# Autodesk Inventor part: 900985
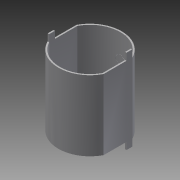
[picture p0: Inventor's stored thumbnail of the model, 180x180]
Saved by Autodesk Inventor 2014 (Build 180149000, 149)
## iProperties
Created: 2007-10
Part Number: 900985
Document SubType Name: Sheet Metal
Designer: TH
Density: 8.08 g/cm^3
Mass: 55.7852 g
Surface Area: 142.634 cm^2
Volume: 6.9041 cm^3
Material: Stainless Steel
Description: MOTOR SLEEVE
Sheet Metal Rule: Default
Appearance: Steel
Component Category: Electrical
Author: TH
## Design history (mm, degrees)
sketch "Sketch1"
  geometry: L1 (-20, 10.061)-(-20, -10.061); L2 (20, 10.061)-(20, -10.061); L3 (-19, 10.061)-(-19, -10.061); L4 (19, -10.062)-(19, 10.061); A1 r 22.5 centre (0, 0) between (-19.883, -10.531) and (19.883, -10.531); A2 r 22.5 centre (0, 0) between (19.883, 10.531) and (-19.883, 10.531); A3 r 21.5 centre (0, 0) between (-18.999, -10.063) and (19, -10.062); A4 r 21.5 centre (0, 0) between (18.999, 10.063) and (-18.999, 10.063); A5 r 0.005 centre (-18.995, 10.061) between (-18.999, 10.063) and (-19, 10.061); A6 r 0.005 centre (18.995, 10.061) between (19, 10.061) and (18.999, 10.063); A7 r 0.005 centre (-18.995, -10.061) between (-19, -10.061) and (-18.999, -10.063); A8 r 1.005 centre (-18.995, 10.061) between (-19.883, 10.531) and (-20, 10.061); A9 r 1.005 centre (-18.995, -10.061) between (-20, -10.061) and (-19.883, -10.531); A10 r 1.005 centre (18.995, -10.061) between (19.883, -10.531) and (20, -10.061); A11 r 1.005 centre (18.995, 10.061) between (20, 10.061) and (19.883, 10.531); 1 further point
  constraints: 22 point on circle, 14 tangent, 11 centre point, 8 end point, 5 equal radius, 2 parallel, 1 coincident, 1 vertical, 3 other
  dimensions: "d1" = 40 distance between parallel lines of L2 L1; "d2" = 20 distance from line of L2 point (0, 0) (= 0.5 x d1); "d3" = 22.5 radius of A2; "d4" = 1 distance between parallel lines of L1 L3; "d17" = 0.005 radius of A5; "d19" = 1.005 radius of A8; "d22" = 22.5 radius of A1 (= d3)
extrude "Extrusion1" new body sketch "Sketch1" stored distance "d5" = 50; taper "d6" = 0 deg
workplane "Work Plane1"
sketch "Sketch2"
  geometry: L1 (0, -35)-(0, 35) reference; L2 (-28, 0)-(28, 0) reference; L3 (19.883, 25)-(-19.883, 25) reference; L4 (-19.883, 25)-(19.883, 25) reference; L5 (-4, 25)-(-4, 10.887); L6 (-2.5, 10.021)-(-1.5, 10.598); L7 (1.5, 5.402)-(-3.5, 2.515); L8 (-4, 1.649)-(-4, 0); L9 (-4.1, 0)-(-4.1, 1.649); L10 (-3.55, 2.602)-(1.45, 5.489); L11 (-1.45, 10.511)-(-2.45, 9.934); L12 (-4.1, 10.887)-(-4.1, 25); L13 (-4, -25)-(-4, -10.887); L14 (-4.1, -10.887)-(-4.1, -25); L15 (-2.5, -10.021)-(-1.5, -10.598); L16 (-1.45, -10.511)-(-2.45, -9.934); L17 (-3.55, -2.602)-(1.45, -5.489); L18 (1.5, -5.402)-(-3.5, -2.515); L19 (-4, -1.649)-(-4, 0); L20 (-4.1, 0)-(-4.1, -1.649); L21 (-4, -25)-(-4.1, -25); L22 (-4.1, 25)-(-4, 25); L23 (20, 25)-(19.883, 25) reference; L24 (19.883, 25)-(20, 25) reference; L25 (-20, 25)-(-19.883, 25) reference; L26 (-19.883, 25)-(-20, 25) reference; A1 r 3 centre (0, 8) between (1.5, 5.402) and (-1.5, 10.598); A2 r 1 centre (-3, 10.887) between (-4, 10.887) and (-2.5, 10.021); A3 r 1 centre (-3, 1.649) between (-3.5, 2.515) and (-4, 1.649); A4 r 1.1 centre (-3, 1.649) between (-3.55, 2.602) and (-4.1, 1.649); A5 r 2.9 centre (0, 8) between (1.45, 5.489) and (-1.45, 10.511); A6 r 1.1 centre (-3, 10.887) between (-4.1, 10.887) and (-2.45, 9.934); A7 r 1 centre (-3, -10.887) between (-2.5, -10.021) and (-4, -10.887); A8 r 1.1 centre (-3, -10.887) between (-2.45, -9.934) and (-4.1, -10.887); A9 r 3 centre (0, -8) between (-1.5, -10.598) and (1.5, -5.402); A10 r 2.9 centre (0, -8) between (-1.45, -10.511) and (1.45, -5.489); A11 r 1.1 centre (-3, -1.649) between (-4.1, -1.649) and (-3.55, -2.602); A12 r 1 centre (-3, -1.649) between (-4, -1.649) and (-3.5, -2.515); 1 further point
  constraints: 36 end point, 24 point on circle, 17 symmetric about line, 12 centre point, 6 tangent, 3 parallel, 3 point on line, 2 collinear, 2 perpendicular, 12 other
  dimensions: "d8" = 60 deg angle of L6 L5; "d9" = 6 diameter of A1; "d11" = 4 distance between parallel lines of L1 L5; "d12" = 1 radius of A2; "d13" = 1 radius of A3; "d14" = 0.1 distance between parallel lines of L5 L12; "d21" = 14.11325 distance from line of A2.centre L3
cut "Cut1" sketch "Sketch2" dims "d15" = 3, "d16" = 0
sketch "Sketch3"
  geometry: L1 (-20, -10.061)-(-20, 10.061) reference; L2 (20, 10.061)-(20, -10.061) reference; L3 (18.995, -10.061)-(20, -10.061); L4 (20, -10.061)-(20, -6); L5 (20, -6)-(18.995, -6); L6 (18.995, -6)-(18.995, -10.061); L7 (-18.995, 10.061)-(-20, 10.061); L8 (-20, 10.061)-(-20, 6); L9 (-20, 6)-(-18.995, 6); L10 (-18.995, 6)-(-18.995, 10.061); A1 r 22.5 centre (0, 0) between (-4.1, 22.123) and (-19.883, 10.531) reference; A2 r 0.005 centre (18.995, -10.061) between (18.999, -10.063) and (19, -10.061) reference; A3 r 0.005 centre (-18.995, 10.061) between (-18.999, 10.063) and (-19, 10.061) reference
  constraints: 16 end point, 4 parallel, 2 horizontal, 2 perpendicular, 2 point on line
  dimensions: "d23" = 6 distance from line of A1.centre L5; "d24" = 6 distance from line of A1.centre L9 (= d23)
extrude "Extrusion2" join sketch "Sketch3" distance "d25" = 5; taper "d26" = 0 deg
mirror "Mirror1"
body "Solid1"
node "Projected Loop1"
other parameters: "Thickness" = 1, "BendRadius" = 1 (= Thickness), "BendReliefWidth" = 1 (= Thickness), "BendReliefDepth" = 0.5 (= 0.5 x Thickness), "CornerReliefSize" = 4 (= 4 x Thickness), "SeamGap" = 0.01, "MinimumRemnant" = 2 (= 2 x Thickness), "TransitionRadius" = 1 (= BendRadius), "JacobiRadiusSize" = 1 (= Thickness), "d0" = 35, "d20" = 22.5, "GapSize" = 1 (= Thickness)
